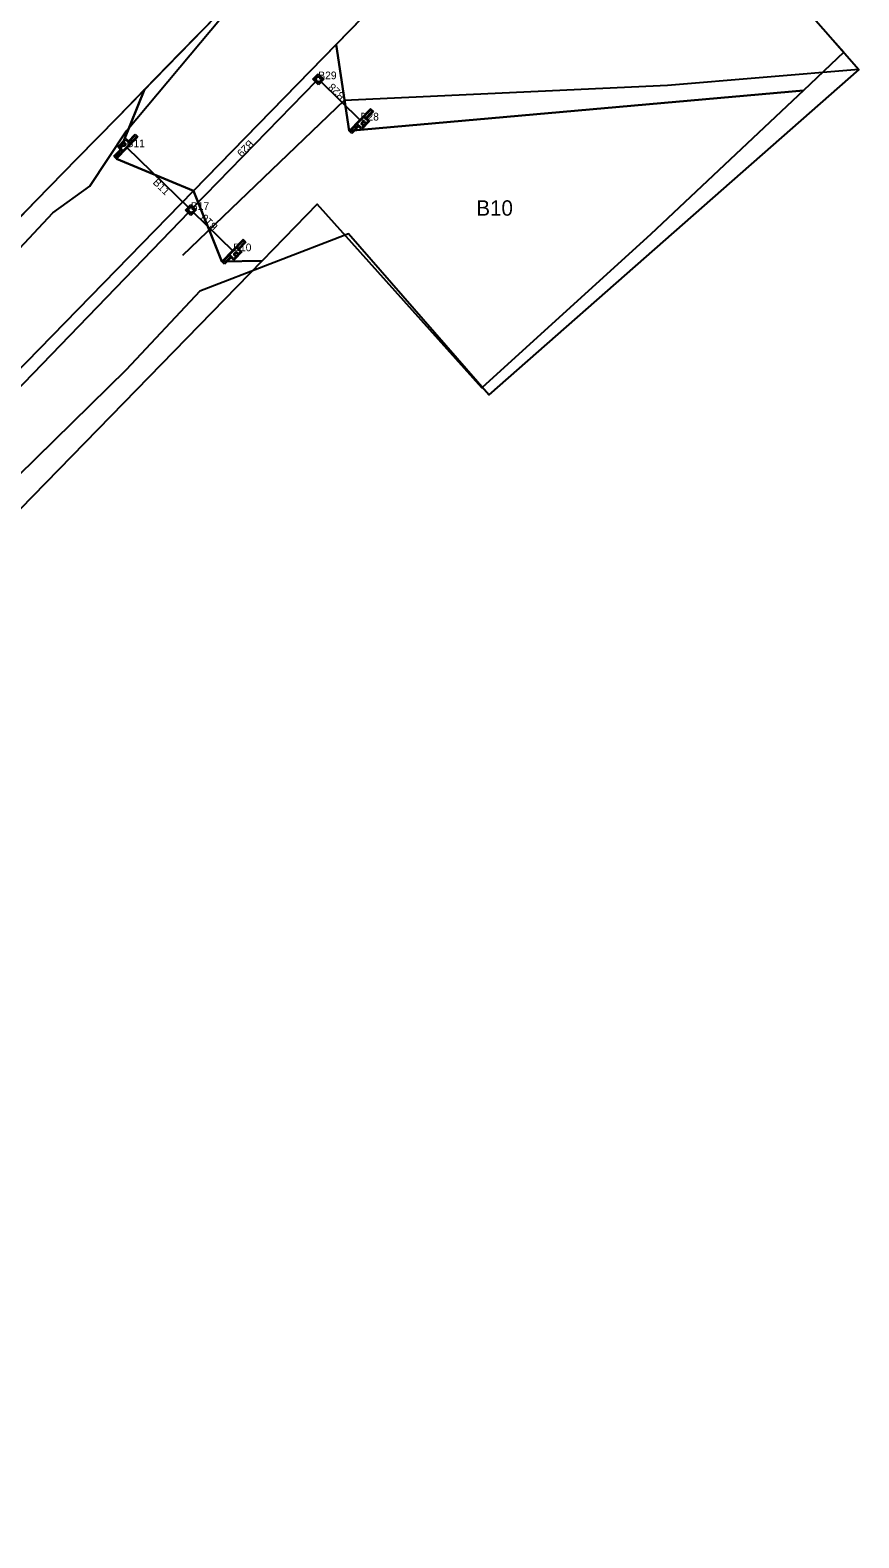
# Model space of a CAD drawing. Extents: x 2253035 to 2279930, y 13774972 to 13793443.
# Drawn here: x 2256071 to 2256503, y 13791353 to 13792138 of the extents above; entities that cross this region are included whole.
import ezdxf

# ---------------------------------------------------------------- set-up
doc = ezdxf.new("R2010")
doc.units = 0
for name, color, linetype in [('E_Utility_ATT_Fiber', 7, 'Continuous'), ('E_Utility_ATT_Xbox', 7, 'Continuous'), ('E_Utility_Fiber Optic_Fiber Optic Cable_FOC', 7, 'Continuous'), ('E_Utility_Gas_Gas Line_GL_Description', 7, 'Continuous'), ('E_Utility_Gas_Gas Line_GL_Elevation', 7, 'Continuous'), ('E_Utility_Water_Valve Cover Water_VCW_point', 7, 'Continuous'), ('E_Utility_Water_Water Line_WL_Elevation', 7, 'Continuous'), ('E_Utility_Water_Water Valve_WV_Elevation', 7, 'Continuous')]:
    doc.layers.add(name, color=color, linetype=linetype)

msp = doc.modelspace()

# ---------------------------------------------------------------- linework, layer by layer
at = {"layer": 'E_Utility_ATT_Fiber'}
for p, q in [((2256116.82, 13792092.37), (2256168.34, 13792145.2)), ((2256130.95, 13792106.86), (2256116.82, 13792092.37)), ((2256095.89, 13792070.91), (2256116.82, 13792092.37)), ((2256116.82, 13792092.37), (2256095.89, 13792070.91)), ((2256074.64, 13792049.12), (2256095.89, 13792070.91)), ((2256095.89, 13792070.91), (2256074.64, 13792049.12)), ((2256043.35, 13792017.03), (2256074.64, 13792049.12)), ((2256074.64, 13792049.12), (2256043.35, 13792017.03))]:
    msp.add_line(p, q, dxfattribs=at)
for points in [[(2256149.38, 13792125.76), (2256130.95, 13792106.86), (2256116.36, 13792070.77), (2256156.41, 13792054.2), (2256366.76, 13792269.87), (2256287.39, 13792357.24), (2256249.05, 13792318.61), (2256259.48, 13792247.85), (2256249.69, 13792232.65), (2256192.81, 13792170.29), (2256178.77, 13792155.88)], [(2256366.76, 13792269.87), (2256494.93, 13792126.24), (2256473.83, 13792106.34), (2256237.46, 13792085.37), (2256230.65, 13792130.31)], [(2256230.65, 13792130.31), (2256237.46, 13792085.37), (2256473.83, 13792106.34), (2256394.53, 13792031.55), (2256306.5, 13791951.66), (2256220.83, 13792047.2), (2256192.1, 13792017.74), (2256171.13, 13792017.36), (2256156.41, 13792054.2)], [(2256171.13, 13792017.36), (2256192.1, 13792017.74), (2256119.93, 13791943.73), (2256025.48, 13791846.89), (2255967.21, 13791785.59), (2255941.93, 13791781.43), (2255934.04, 13791825.57), (2255989.41, 13791882.95), (2256156.41, 13792054.2)]]:
    msp.add_lwpolyline(points, close=True, dxfattribs=at)
for points in [[(2256156.41, 13792054.2), (2256116.36, 13792070.77), (2256130.95, 13792106.86)], [(2255934.04, 13791825.57), (2255989.41, 13791882.95), (2256156.41, 13792054.2)]]:
    msp.add_lwpolyline(points, dxfattribs=at)
at = {"layer": 'E_Utility_ATT_Xbox'}
for p, q in [((2256220.31, 13792113.27), (2256220.31, 13792113.27)), ((2256220.34, 13792111.14), (2256220.34, 13792111.14)), ((2256221.38, 13792112.22), (2256221.38, 13792112.22)), ((2256222.43, 13792113.29), (2256222.43, 13792113.29)), ((2256222.46, 13792111.17), (2256222.46, 13792111.17)), ((2256246.22, 13792091.49), (2256246.22, 13792091.49)), ((2256242.73, 13792087.91), (2256242.73, 13792087.91)), ((2256243.4, 13792090.75), (2256243.4, 13792090.75)), ((2256244.47, 13792089.7), (2256244.47, 13792089.7)), ((2256245.55, 13792088.65), (2256245.55, 13792088.65)), ((2256118.77, 13792076.1), (2256118.77, 13792076.1)), ((2256119.44, 13792078.94), (2256119.44, 13792078.94)), ((2256120.51, 13792077.89), (2256120.51, 13792077.89)), ((2256121.59, 13792076.85), (2256121.59, 13792076.85)), ((2256122.26, 13792079.68), (2256122.26, 13792079.68)), ((2256153.98, 13792045.25), (2256153.98, 13792045.25)), ((2256155.06, 13792044.21), (2256155.06, 13792044.21)), ((2256156.1, 13792045.28), (2256156.1, 13792045.28)), ((2256154.01, 13792043.13), (2256154.01, 13792043.13)), ((2256156.13, 13792043.16), (2256156.13, 13792043.16)), ((2256177.07, 13792022.74), (2256177.07, 13792022.74)), ((2256178.14, 13792021.69), (2256178.14, 13792021.69)), ((2256179.22, 13792020.64), (2256179.22, 13792020.64)), ((2256179.89, 13792023.48), (2256179.89, 13792023.48)), ((2256176.4, 13792019.9), (2256176.4, 13792019.9))]:
    msp.add_line(p, q, dxfattribs=at)
at = {"layer": 'E_Utility_Fiber Optic_Fiber Optic Cable_FOC'}
for p, q in [((2256218.56, 13792112.18), (2256221.35, 13792115.05)), ((2256219.26, 13792112.19), (2256221.36, 13792114.34)), ((2256221.35, 13792115.05), (2256224.21, 13792112.25)), ((2256221.36, 13792114.34), (2256223.51, 13792112.24)), ((2256221.42, 13792109.39), (2256218.56, 13792112.18)), ((2256221.41, 13792110.1), (2256219.26, 13792112.19)), ((2256223.51, 13792112.24), (2256221.41, 13792110.1)), ((2256224.21, 13792112.25), (2256221.42, 13792109.39)), ((2256248.63, 13792096.82), (2256237.46, 13792085.37)), ((2256248.64, 13792096.12), (2256238.16, 13792085.38)), ((2256247.29, 13792090.44), (2256244.79, 13792092.89)), ((2256246.57, 13792091.85), (2256245.14, 13792093.25)), ((2256249.35, 13792095.42), (2256245.86, 13792091.84)), ((2256250.06, 13792095.43), (2256246.57, 13792091.85)), ((2256248, 13792090.45), (2256246.57, 13792091.85)), ((2256249.35, 13792095.42), (2256248.28, 13792096.47)), ((2256250.06, 13792095.43), (2256248.63, 13792096.82)), ((2256122.61, 13792080.04), (2256126.1, 13792083.62)), ((2256126.1, 13792083.62), (2256127.53, 13792082.22)), ((2256238.89, 13792083.97), (2256237.46, 13792085.37)), ((2256238.88, 13792084.68), (2256237.8, 13792085.73)), ((2256242.37, 13792088.26), (2256238.88, 13792084.68)), ((2256242.38, 13792087.55), (2256238.89, 13792083.97)), ((2256242.38, 13792087.55), (2256240.95, 13792088.95)), ((2256243.8, 13792086.86), (2256241.3, 13792089.31)), ((2256243.81, 13792086.16), (2256242.38, 13792087.55)), ((2256247.29, 13792090.44), (2256243.8, 13792086.86)), ((2256248, 13792090.45), (2256243.81, 13792086.16)), ((2256114.93, 13792072.17), (2256118.42, 13792075.75)), ((2256115.64, 13792072.18), (2256119.13, 13792075.76)), ((2256116.35, 13792071.48), (2256126.82, 13792082.22)), ((2256116.36, 13792070.77), (2256127.53, 13792082.22)), ((2256116.99, 13792077.14), (2256121.18, 13792081.44)), ((2256116.99, 13792077.14), (2256118.42, 13792075.75)), ((2256117.69, 13792077.15), (2256121.19, 13792080.73)), ((2256117.69, 13792077.15), (2256120.2, 13792074.71)), ((2256118.42, 13792075.75), (2256119.85, 13792074.35)), ((2256121.18, 13792081.44), (2256122.61, 13792080.04)), ((2256121.19, 13792080.73), (2256123.69, 13792078.29)), ((2256122.61, 13792080.04), (2256124.04, 13792078.65)), ((2256122.62, 13792079.33), (2256126.11, 13792082.91)), ((2256126.11, 13792082.91), (2256127.18, 13792081.87)), ((2256114.93, 13792072.17), (2256116.36, 13792070.77)), ((2256115.64, 13792072.18), (2256116.71, 13792071.13)), ((2256152.23, 13792044.17), (2256155.02, 13792047.03)), ((2256155.09, 13792041.38), (2256152.23, 13792044.17)), ((2256152.94, 13792044.18), (2256155.03, 13792046.33)), ((2256155.08, 13792042.09), (2256152.94, 13792044.18)), ((2256155.02, 13792047.03), (2256157.88, 13792044.24)), ((2256155.03, 13792046.33), (2256157.18, 13792044.23)), ((2256157.18, 13792044.23), (2256155.08, 13792042.09)), ((2256157.88, 13792044.24), (2256155.09, 13792041.38)), ((2256182.3, 13792028.81), (2256171.13, 13792017.36)), ((2256182.31, 13792028.11), (2256171.83, 13792017.37)), ((2256183.02, 13792027.41), (2256181.95, 13792028.46)), ((2256183.73, 13792027.42), (2256182.3, 13792028.81)), ((2256176.04, 13792020.25), (2256172.55, 13792016.67)), ((2256176.05, 13792019.54), (2256174.62, 13792020.94)), ((2256177.47, 13792018.85), (2256174.97, 13792021.3)), ((2256180.96, 13792022.43), (2256177.47, 13792018.85)), ((2256181.67, 13792022.44), (2256177.48, 13792018.15)), ((2256180.96, 13792022.43), (2256178.46, 13792024.88)), ((2256180.24, 13792023.84), (2256178.81, 13792025.23)), ((2256183.02, 13792027.41), (2256179.53, 13792023.83)), ((2256183.73, 13792027.42), (2256180.24, 13792023.84)), ((2256181.67, 13792022.44), (2256180.24, 13792023.84)), ((2256172.56, 13792015.96), (2256171.13, 13792017.36)), ((2256172.55, 13792016.67), (2256171.48, 13792017.72)), ((2256176.05, 13792019.54), (2256172.56, 13792015.96)), ((2256177.48, 13792018.15), (2256176.05, 13792019.54))]:
    msp.add_line(p, q, dxfattribs=at)
for centre, radius in [((2256221.62, 13792112.22), 1.67), ((2256221.62, 13792112.22), 1.33), ((2256245.01, 13792089.18), 1.08), ((2256245.01, 13792089.18), 0.75), ((2256119.98, 13792078.42), 1.08), ((2256119.98, 13792078.42), 0.75), ((2256155.29, 13792044.21), 1.67), ((2256155.29, 13792044.21), 1.33), ((2256178.68, 13792021.17), 1.08), ((2256178.68, 13792021.17), 0.75)]:
    msp.add_circle(centre, radius, dxfattribs=at)
at = {"layer": 'E_Utility_Gas_Gas Line_GL_Description'}
for p, q in [((2256220.34, 13792111.14), (2256156.1, 13792045.28)), ((2256243.4, 13792090.75), (2256222.46, 13792111.17)), ((2256121.59, 13792076.85), (2256153.98, 13792045.25)), ((2256154.01, 13792043.13), (2255927.7, 13791808.58)), ((2256177.07, 13792022.74), (2256156.13, 13792043.16))]:
    msp.add_line(p, q, dxfattribs=at)
at = {"layer": 'E_Utility_Water_Valve Cover Water_VCW_point'}
for p, q in [((2256502.73, 13792117.35), (2256403.09, 13792108.88)), ((2256403.09, 13792108.88), (2256234.83, 13792101.12)), ((2256234.83, 13792101.12), (2256150.65, 13792020.6))]:
    msp.add_line(p, q, dxfattribs=at)
at = {"layer": 'E_Utility_Water_Water Line_WL_Elevation'}
msp.add_lwpolyline([(2255552.69, 13792209.6), (2255414.64, 13792056.03), (2255343.69, 13791984.84), (2255605.99, 13791701.86), (2255609.85, 13791705.81), (2255620.44, 13791716), (2255687.16, 13791650.79), (2255732.69, 13791697.37), (2255738.56, 13791691.61), (2255743.07, 13791696.22), (2255737.22, 13791701.96), (2255882.44, 13791850.6), (2255952.2, 13791922.14), (2256017.05, 13791988.64), (2256050.99, 13792008.43), (2256083.27, 13792042.75), (2256102.42, 13792056.55), (2256121.52, 13792085.4), (2256170.83, 13792144.18)], dxfattribs=at)
at = {"layer": 'E_Utility_Water_Water Valve_WV_Elevation'}
msp.add_lwpolyline([(2255390.98, 13791330.06), (2255459.85, 13791397.22), (2255383.32, 13791459.9), (2255493.57, 13791567.11), (2255547.29, 13791645.62), (2255605.99, 13791701.86), (2255343.69, 13791984.84), (2255414.64, 13792056.03), (2255552.69, 13792209.6), (2256003.03, 13792697.26), (2256274.85, 13792371.04), (2256429.6, 13792200.7), (2256502.73, 13792117.35), (2256310.07, 13791948.12), (2256237.1, 13792031.76), (2256159.74, 13792001.95), (2256121.45, 13791961.04), (2255952.32, 13791795.31), (2255623, 13791457.45), (2255517, 13791344.43)], dxfattribs=at)

# ---------------------------------------------------------------- texts
at = {"layer": 'E_Utility_Gas_Gas Line_GL_Elevation'}
for s, height, p in [('B29', 4, (2256221.38, 13792112.22)), ('B28', 4, (2256243.4, 13792090.75)), ('B11', 4, (2256121.59, 13792076.85)), ('B17', 4, (2256155.06, 13792044.21)), ('B10', 8, (2256303.64, 13792041.24)), ('B10', 4, (2256177.07, 13792022.74))]:
    msp.add_text(s, height=height, dxfattribs=at).set_placement(p)
for s, rotation, p in [('B28', 135.71793, (2256235.72, 13792103.82)), ('B29', 225.71793, (2256185.36, 13792081)), ('B11', 315.71793, (2256134.99, 13792058.19)), ('B10', 135.71793, (2256169.39, 13792035.81))]:
    msp.add_text(s, height=4, rotation=rotation, dxfattribs=at).set_placement(p)

doc.saveas('drawing.dxf')
